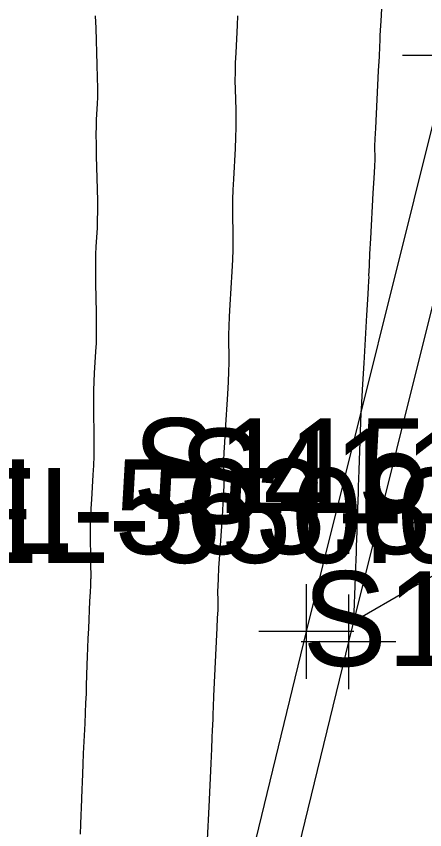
# Model space of a CAD drawing. Extents: x 1724534 to 1727318, y 657156 to 660047.
# Drawn here: x 1725468.3 to 1725485.54, y 659145.59 to 659179.92 of the extents above; entities that cross this region are included whole.
import ezdxf

# ---------------------------------------------------------------- set-up
doc = ezdxf.new("R2010")
doc.units = 0
for name, color, linetype in [('SURVEY - CENTERLINE - Preliminary', 7, 'Continuous'), ('SURVEY - CONTOURS - Intermediate with optional Text', 7, 'Continuous'), ('SURVEY - DTM - Breaklines', 7, 'Continuous'), ('SURVEY - DTM - Breaklines - Points - Elevations', 7, 'Continuous'), ('SURVEY - DTM - Breaklines - Points - Locators', 7, 'Continuous'), ('SURVEY - DTM - Breaklines - Points - Numbers', 7, 'Continuous'), ('SURVEY - NON-TRANSPORTATION - Features - Points - Elevations', 7, 'Continuous'), ('SURVEY - TRANSPORTATION - Features', 7, 'Continuous'), ('SURVEY - TRANSPORTATION - Features - Points - Locators', 7, 'Continuous'), ('SURVEY - TRANSPORTATION - Features - Points - Numbers', 7, 'Continuous'), ('SURVEY - TRANSPORTATION - Roads - Points - Numbers', 7, 'Continuous')]:
    doc.layers.add(name, color=color, linetype=linetype)

msp = doc.modelspace()

# ---------------------------------------------------------------- linework, layer by layer
at = {"layer": 'SURVEY - CENTERLINE - Preliminary'}
msp.add_arc((1727061.077, 658773.081), 1600, 165.79242, 172.785391, dxfattribs=at)
msp.add_arc((1727061.077, 658773.081), 1600, 165.79242, 172.785391, dxfattribs=at)
msp.add_arc((1727061.077, 658773.081), 1600, 165.79242, 172.785391, dxfattribs=at)
at = {"layer": 'SURVEY - CONTOURS - Intermediate with optional Text'}
for points in [[(1725483.713, 659180.258), (1725483.686, 659179.717), (1725483.666, 659179.33), (1725483.654, 659179.098), (1725483.651, 659179.021), (1725483.651, 659179.02), (1725483.651, 659179.02), (1725483.651, 659179.018), (1725483.651, 659179.014), (1725483.651, 659179.009), (1725483.652, 659178.995), (1725483.647, 659178.905), (1725483.635, 659178.646), (1725483.613, 659178.219), (1725483.582, 659177.623), (1725483.49, 659175.808), (1725483.46, 659175.203), (1725483.439, 659174.746), (1725483.428, 659174.439), (1725483.426, 659174.282), (1725483.433, 659174.061), (1725483.431, 659173.898), (1725483.417, 659173.577), (1725483.393, 659173.096), (1725483.359, 659172.456), (1725483.253, 659170.538), (1725483.218, 659169.903), (1725483.193, 659169.438), (1725483.179, 659169.141), (1725483.175, 659169.014), (1725483.178, 659168.901), (1725483.174, 659168.77), (1725483.157, 659168.459), (1725483.13, 659167.971), (1725483.091, 659167.304), (1725482.97, 659165.287), (1725482.931, 659164.625), (1725482.903, 659164.151), (1725482.886, 659163.865), (1725482.881, 659163.767), (1725482.881, 659163.756), (1725482.88, 659163.741), (1725482.878, 659163.707), (1725482.875, 659163.652), (1725482.87, 659163.577), (1725482.845, 659163.18), (1725482.777, 659161.172), (1725482.763, 659160.764), (1725482.751, 659160.402), (1725482.74, 659160.084), (1725482.731, 659159.811), (1725482.707, 659159.143), (1725482.699, 659158.894), (1725482.69, 659158.649), (1725482.682, 659158.409), (1725482.674, 659158.172), (1725482.652, 659157.547), (1725482.644, 659157.291), (1725482.633, 659156.992), (1725482.621, 659156.651), (1725482.608, 659156.267), (1725482.541, 659154.374), (1725484.967, 659155.781), (1725485.468, 659156.069), (1725485.929, 659156.333)], [(1725471.636, 659179.945), (1725471.652, 659179.415), (1725471.703, 659177.876), (1725471.717, 659177.34), (1725471.724, 659176.886), (1725471.723, 659176.515), (1725471.713, 659176.227), (1725471.677, 659175.567), (1725471.666, 659175.285), (1725471.663, 659174.934), (1725471.667, 659174.514), (1725471.677, 659174.025), (1725471.715, 659172.629), (1725471.725, 659172.134), (1725471.727, 659171.695), (1725471.722, 659171.314), (1725471.708, 659170.989), (1725471.661, 659170.198), (1725471.647, 659169.88), (1725471.639, 659169.517), (1725471.639, 659169.111), (1725471.646, 659168.66), (1725471.672, 659167.4), (1725471.678, 659166.944), (1725471.676, 659166.52), (1725471.667, 659166.128), (1725471.649, 659165.769), (1725471.591, 659164.854), (1725471.572, 659164.501), (1725471.561, 659164.127), (1725471.557, 659163.733), (1725471.56, 659163.319), (1725471.578, 659162.188), (1725471.581, 659161.769), (1725471.575, 659161.358), (1725471.561, 659160.957), (1725471.539, 659160.565), (1725471.47, 659159.532), (1725471.448, 659159.146), (1725471.433, 659158.762), (1725471.425, 659158.38), (1725471.426, 659158.001), (1725471.436, 659156.992), (1725471.439, 659156.66), (1725471.442, 659156.422), (1725471.443, 659156.276), (1725471.443, 659156.223), (1725471.442, 659156.207), (1725471.441, 659156.201), (1725471.441, 659156.192), (1725471.441, 659156.181), (1725471.44, 659156.169), (1725471.439, 659156.134), (1725471.436, 659156.068), (1725471.428, 659155.897), (1725471.416, 659155.62), (1725471.398, 659155.238), (1725471.344, 659154.08), (1725471.325, 659153.658), (1725471.309, 659153.263), (1725471.295, 659152.895), (1725471.283, 659152.554), (1725471.256, 659151.678), (1725471.244, 659151.332), (1725471.229, 659150.949), (1725471.211, 659150.529), (1725471.19, 659150.074), (1725471.131, 659148.81), (1725471.11, 659148.359), (1725471.092, 659147.955), (1725471.078, 659147.597), (1725471.067, 659147.285), (1725471.043, 659146.515), (1725471.031, 659146.198), (1725471.016, 659145.825), (1725470.998, 659145.396)], [(1725477.641, 659179.938), (1725477.621, 659179.553), (1725477.562, 659178.385), (1725477.544, 659177.96), (1725477.534, 659177.563), (1725477.532, 659177.192), (1725477.539, 659176.848), (1725477.568, 659175.968), (1725477.574, 659175.619), (1725477.571, 659175.231), (1725477.558, 659174.806), (1725477.536, 659174.341), (1725477.465, 659173.052), (1725477.442, 659172.594), (1725477.428, 659172.186), (1725477.423, 659171.828), (1725477.426, 659171.52), (1725477.447, 659170.765), (1725477.449, 659170.452), (1725477.442, 659170.077), (1725477.426, 659169.642), (1725477.399, 659169.146), (1725477.316, 659167.743), (1725477.289, 659167.253), (1725477.271, 659166.834), (1725477.263, 659166.488), (1725477.263, 659166.214), (1725477.277, 659165.578), (1725477.277, 659165.298), (1725477.266, 659164.937), (1725477.246, 659164.493), (1725477.215, 659163.967), (1725477.119, 659162.455), (1725477.088, 659161.934), (1725477.066, 659161.506), (1725477.055, 659161.171), (1725477.053, 659160.928), (1725477.061, 659160.406), (1725477.059, 659160.158), (1725477.045, 659159.809), (1725477.021, 659159.356), (1725476.986, 659158.802), (1725476.877, 659157.186), (1725476.842, 659156.637), (1725476.817, 659156.199), (1725476.802, 659155.875), (1725476.799, 659155.663), (1725476.803, 659155.247), (1725476.804, 659155.11), (1725476.805, 659155.009), (1725476.805, 659154.945), (1725476.805, 659154.918), (1725476.803, 659154.894), (1725476.803, 659154.885), (1725476.802, 659154.878), (1725476.802, 659154.871), (1725476.802, 659154.865), (1725476.786, 659154.518), (1725476.767, 659154.11), (1725476.66, 659151.808), (1725476.633, 659151.226), (1725476.613, 659150.778), (1725476.599, 659150.464), (1725476.592, 659150.284), (1725476.583, 659149.984), (1725476.576, 659149.799), (1725476.561, 659149.471), (1725476.54, 659148.999), (1725476.511, 659148.383), (1725476.424, 659146.549), (1725476.36, 659145.176)]]:
    msp.add_lwpolyline(points, dxfattribs=at)
at = {"layer": 'SURVEY - DTM - Breaklines'}
msp.add_lwpolyline([(1725504.884, 659250.966), (1725498.725, 659226.793), (1725492.704, 659202.503), (1725486.609, 659178.27), (1725480.544, 659153.955), (1725474.624, 659129.616), (1725468.741, 659105.278), (1725462.975, 659080.964), (1725457.482, 659056.509), (1725452.226, 659031.922), (1725447.641, 659009.959), (1725446.425, 659003.851), (1725441.811, 658979.15), (1725437.527, 658954.376), (1725432.503, 658922.481), (1725434.197, 658921.722)], dxfattribs=at)
at = {"layer": 'SURVEY - DTM - Breaklines - Points - Locators'}
for p, q in [((1725488.609, 659178.27), (1725484.609, 659178.27)), ((1725480.544, 659155.955), (1725480.544, 659151.955)), ((1725482.544, 659153.955), (1725478.544, 659153.955))]:
    msp.add_line(p, q, dxfattribs=at)
at = {"layer": 'SURVEY - TRANSPORTATION - Features'}
msp.add_lwpolyline([(1725506.673, 659250.514), (1725500.512, 659226.334), (1725494.493, 659202.049), (1725488.389, 659177.819), (1725482.327, 659153.516), (1725476.395, 659129.191), (1725470.514, 659104.862), (1725464.748, 659080.55), (1725459.259, 659056.109), (1725454.008, 659031.549), (1725449.429, 659009.612), (1725448.213, 659003.504), (1725443.603, 658978.829), (1725439.325, 658954.082), (1725434.304, 658922.209), (1725434.197, 658921.722)], dxfattribs=at)
at = {"layer": 'SURVEY - TRANSPORTATION - Features - Points - Locators'}
for p, q in [((1725482.327, 659155.516), (1725482.327, 659151.516)), ((1725484.327, 659153.516), (1725480.327, 659153.516))]:
    msp.add_line(p, q, dxfattribs=at)

# ---------------------------------------------------------------- texts
at = {"layer": 'SURVEY - DTM - Breaklines - Points - Elevations'}
msp.add_text('EL-563.89', height=4, dxfattribs=at).set_placement((1725464.12, 659157.228))
at = {"layer": 'SURVEY - DTM - Breaklines - Points - Numbers'}
msp.add_text('S115', height=4, dxfattribs=at).set_placement((1725473.208, 659158.955))
at = {"layer": 'SURVEY - NON-TRANSPORTATION - Features - Points - Elevations'}
msp.add_text('EL-550.01', height=4, dxfattribs=at).set_placement((1725465.644, 659156.853))
at = {"layer": 'SURVEY - TRANSPORTATION - Features - Points - Numbers'}
msp.add_text('S411', height=4, dxfattribs=at).set_placement((1725475.149, 659158.516))
at = {"layer": 'SURVEY - TRANSPORTATION - Roads - Points - Numbers'}
msp.add_text('S1383', height=4, dxfattribs=at).set_placement((1725480.378, 659152.5))

doc.saveas('drawing.dxf')
